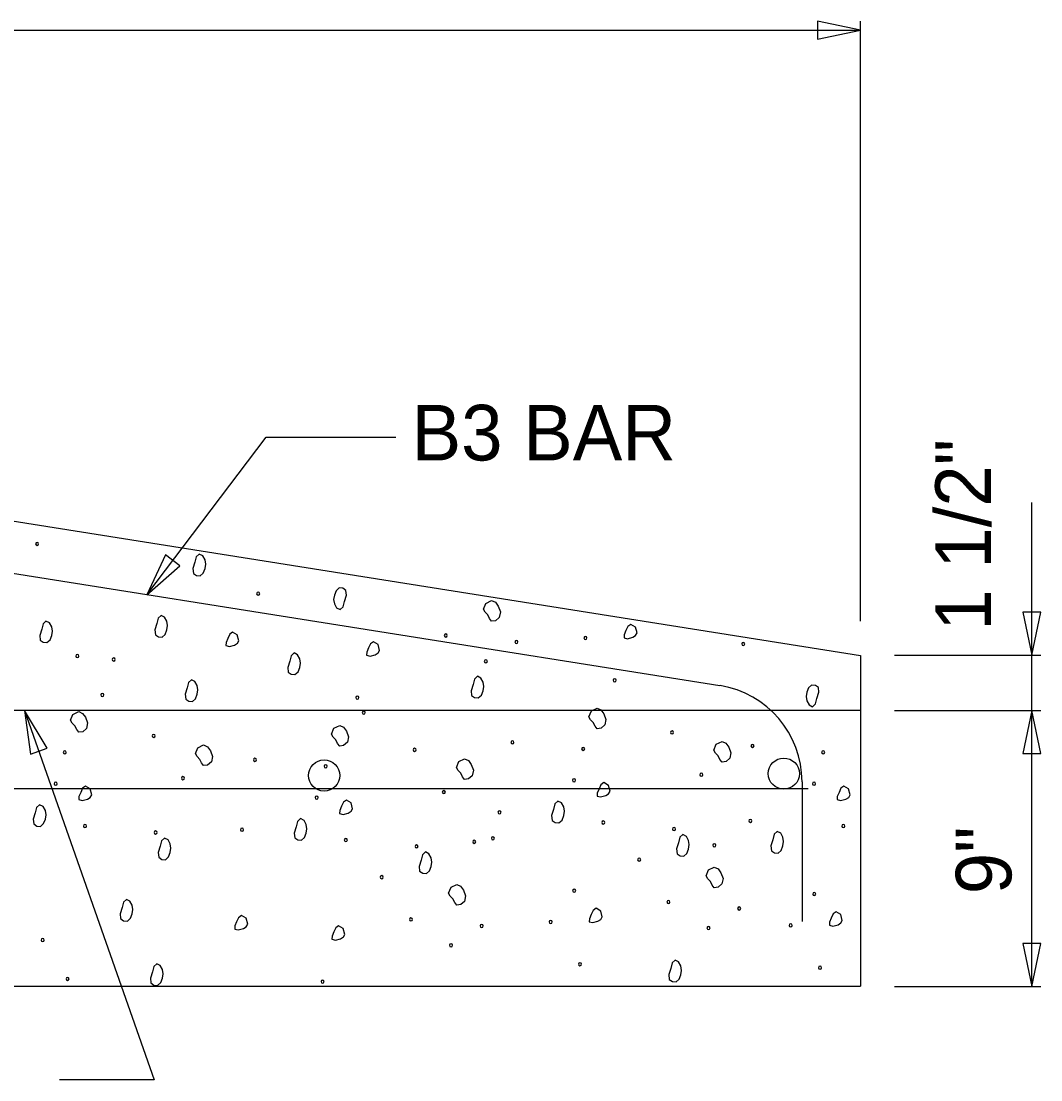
# Model space of a CAD drawing. Extents: x -439.1 to -407.9, y -458.1 to -436.2.
# Drawn here: x -419.155 to -416.404, y -449.316 to -446.46 of the extents above; entities that cross this region are included whole.
import ezdxf

# ---------------------------------------------------------------- set-up
doc = ezdxf.new("R2010")
doc.units = 0
doc.layers.add('Level 4', color=7, linetype='Continuous')
doc.layers.add('Level 45', color=7, linetype='Continuous')

msp = doc.modelspace()

# ---------------------------------------------------------------- linework, layer by layer
at = {"layer": 'Level 4'}
for p, q in [((-422.391, -446.484), (-416.8905, -446.484)), ((-416.8905, -448.0784), (-416.8905, -446.4599)), ((-423.8016, -447.0755), (-416.8905, -448.1707)), ((-421.8946, -447.5188), (-417.2694, -448.2521)), ((-418.8159, -448.0069), (-418.4942, -447.5818)), ((-418.4942, -447.5818), (-418.144, -447.5818)), ((-416.4279, -448.3192), (-416.4279, -447.7581)), ((-416.8905, -448.1707), (-416.8905, -449.0632)), ((-416.7987, -448.1703), (-416.4038, -448.1703)), ((-423.8016, -448.3187), (-416.8905, -448.3187)), ((-419.1455, -448.3192), (-418.7961, -449.3155)), ((-416.7987, -448.3192), (-416.4038, -448.3192)), ((-416.4279, -449.0637), (-416.4279, -448.3192)), ((-417.048, -448.5114), (-417.048, -448.8889)), ((-423.8016, -448.5298), (-417.0312, -448.5298)), ((-423.8016, -449.0632), (-416.8905, -449.0632)), ((-416.7987, -449.0637), (-416.4038, -449.0637)), ((-418.7961, -449.3155), (-419.0512, -449.3155))]:
    msp.add_line(p, q, dxfattribs=at)
for points in [[(-417.0067, -446.5081), (-416.8905, -446.484), (-417.0067, -446.4599)], [(-418.7651, -447.8997), (-418.8159, -448.0069), (-418.7266, -447.9288)], [(-418.6744, -447.8974), (-418.6823, -447.9049), (-418.6861, -447.9195), (-418.6914, -447.9363), (-418.69, -447.9493), (-418.6818, -447.9549), (-418.6718, -447.9558), (-418.6634, -447.9484), (-418.6588, -447.9364), (-418.657, -447.9246), (-418.6588, -447.913), (-418.6648, -447.9022), (-418.6744, -447.8974)], [(-418.2944, -448.0472), (-418.2864, -448.0397), (-418.2827, -448.0251), (-418.2774, -448.0083), (-418.2788, -447.9952), (-418.287, -447.9896), (-418.297, -447.9888), (-418.3054, -447.9961), (-418.3099, -448.0082), (-418.3118, -448.02), (-418.3099, -448.0316), (-418.3039, -448.0424), (-418.2944, -448.0472)], [(-417.9079, -448.046), (-417.9013, -448.0303), (-417.8858, -448.0227), (-417.8755, -448.0275), (-417.8677, -448.0383), (-417.862, -448.0535), (-417.8651, -448.0681), (-417.8751, -448.077), (-417.8858, -448.0785), (-417.8913, -448.0714), (-417.8962, -448.0616), (-417.9032, -448.054), (-417.9079, -448.046)], [(-416.452, -448.0541), (-416.4279, -448.1703), (-416.4038, -448.0541)], [(-419.0879, -448.0779), (-419.0958, -448.0853), (-419.0995, -448.0999), (-419.1048, -448.1167), (-419.1034, -448.1298), (-419.0952, -448.1354), (-419.0853, -448.1363), (-419.0768, -448.1289), (-419.0723, -448.1168), (-419.0705, -448.1051), (-419.0723, -448.0934), (-419.0783, -448.0826), (-419.0879, -448.0779)], [(-418.7772, -448.063), (-418.7852, -448.0704), (-418.7889, -448.085), (-418.7942, -448.1018), (-418.7928, -448.1149), (-418.7846, -448.1205), (-418.7747, -448.1214), (-418.7662, -448.114), (-418.7617, -448.1019), (-418.7598, -448.0902), (-418.7617, -448.0785), (-418.7677, -448.0677), (-418.7772, -448.063)], [(-417.5102, -448.0869), (-417.5179, -448.0928), (-417.5231, -448.1038), (-417.5279, -448.115), (-417.5283, -448.1232), (-417.5188, -448.1256), (-417.505, -448.1219), (-417.4972, -448.1172), (-417.4933, -448.1102), (-417.4975, -448.0943), (-417.5102, -448.0869)], [(-418.5844, -448.1078), (-418.5922, -448.1137), (-418.5974, -448.1247), (-418.6022, -448.136), (-418.6026, -448.1442), (-418.5931, -448.1465), (-418.5792, -448.1429), (-418.5715, -448.1381), (-418.5676, -448.1312), (-418.5718, -448.1153), (-418.5844, -448.1078)], [(-418.2047, -448.1338), (-418.2125, -448.1397), (-418.2177, -448.1507), (-418.2225, -448.1619), (-418.2229, -448.1702), (-418.2134, -448.1725), (-418.1995, -448.1689), (-418.1918, -448.1641), (-418.1878, -448.1572), (-418.1921, -448.1412), (-418.2047, -448.1338)], [(-418.4187, -448.1641), (-418.4266, -448.1716), (-418.4304, -448.1862), (-418.4357, -448.203), (-418.4343, -448.216), (-418.4261, -448.2216), (-418.4161, -448.2225), (-418.4077, -448.2151), (-418.4031, -448.2031), (-418.4013, -448.1913), (-418.4031, -448.1797), (-418.4091, -448.1689), (-418.4187, -448.1641)], [(-417.9241, -448.227), (-417.9321, -448.2344), (-417.9358, -448.2491), (-417.9411, -448.2658), (-417.9397, -448.2789), (-417.9315, -448.2845), (-417.9216, -448.2854), (-417.9131, -448.278), (-417.9086, -448.2659), (-417.9067, -448.2542), (-417.9086, -448.2426), (-417.9146, -448.2317), (-417.9241, -448.227)], [(-418.6955, -448.2364), (-418.7034, -448.2438), (-418.7072, -448.2584), (-418.7125, -448.2752), (-418.711, -448.2883), (-418.7029, -448.2939), (-418.6929, -448.2948), (-418.6844, -448.2874), (-418.6799, -448.2753), (-418.6781, -448.2636), (-418.6799, -448.252), (-418.6859, -448.2411), (-418.6955, -448.2364)], [(-417.0195, -448.309), (-417.0115, -448.3015), (-417.0078, -448.2869), (-417.0025, -448.2701), (-417.0039, -448.2571), (-417.0121, -448.2515), (-417.0221, -448.2506), (-417.0305, -448.2579), (-417.035, -448.27), (-417.0369, -448.2818), (-417.035, -448.2934), (-417.029, -448.3042), (-417.0195, -448.309)], [(-417.623, -448.3361), (-417.6165, -448.3204), (-417.601, -448.3128), (-417.5907, -448.3176), (-417.5828, -448.3283), (-417.5771, -448.3436), (-417.5802, -448.3582), (-417.5902, -448.367), (-417.601, -448.3686), (-417.6064, -448.3615), (-417.6114, -448.3517), (-417.6184, -448.3441), (-417.623, -448.3361)], [(-419.0843, -448.4209), (-419.1455, -448.3192), (-419.1298, -448.4368)], [(-419.0216, -448.3455), (-419.015, -448.3298), (-418.9995, -448.3221), (-418.9892, -448.327), (-418.9813, -448.3377), (-418.9756, -448.353), (-418.9787, -448.3676), (-418.9888, -448.3764), (-418.9995, -448.378), (-419.005, -448.3709), (-419.0099, -448.3611), (-419.0169, -448.3535), (-419.0216, -448.3455)], [(-416.4038, -448.4354), (-416.4279, -448.3192), (-416.452, -448.4354)], [(-418.3176, -448.3831), (-418.311, -448.3673), (-418.2955, -448.3597), (-418.2853, -448.3645), (-418.2774, -448.3753), (-418.2717, -448.3905), (-418.2748, -448.4051), (-418.2848, -448.414), (-418.2955, -448.4155), (-418.301, -448.4084), (-418.3059, -448.3986), (-418.3129, -448.391), (-418.3176, -448.3831)], [(-418.6845, -448.4355), (-418.678, -448.4198), (-418.6625, -448.4121), (-418.6522, -448.417), (-418.6443, -448.4277), (-418.6386, -448.443), (-418.6417, -448.4576), (-418.6517, -448.4664), (-418.6625, -448.468), (-418.6679, -448.4609), (-418.6729, -448.4511), (-418.6799, -448.4435), (-418.6845, -448.4355)], [(-417.286, -448.4261), (-417.2794, -448.4104), (-417.2639, -448.4028), (-417.2536, -448.4076), (-417.2458, -448.4183), (-417.2401, -448.4336), (-417.2432, -448.4482), (-417.2532, -448.457), (-417.2639, -448.4586), (-417.2694, -448.4515), (-417.2743, -448.4417), (-417.2813, -448.4341), (-417.286, -448.4261)], [(-417.9806, -448.4731), (-417.974, -448.4573), (-417.9585, -448.4497), (-417.9482, -448.4545), (-417.9403, -448.4653), (-417.9346, -448.4805), (-417.9377, -448.4951), (-417.9478, -448.504), (-417.9585, -448.5055), (-417.964, -448.4985), (-417.9689, -448.4886), (-417.9759, -448.4811), (-417.9806, -448.4731)], [(-417.5828, -448.5139), (-417.5906, -448.5198), (-417.5958, -448.5308), (-417.6006, -448.542), (-417.601, -448.5502), (-417.5915, -448.5526), (-417.5776, -448.5489), (-417.5699, -448.5442), (-417.5659, -448.5373), (-417.5702, -448.5213), (-417.5828, -448.5139)], [(-418.9814, -448.5233), (-418.9891, -448.5292), (-418.9943, -448.5401), (-418.9991, -448.5514), (-418.9995, -448.5596), (-418.99, -448.562), (-418.9762, -448.5583), (-418.9684, -448.5536), (-418.9645, -448.5466), (-418.9687, -448.5307), (-418.9814, -448.5233)], [(-416.9352, -448.5233), (-416.943, -448.5292), (-416.9481, -448.5401), (-416.9529, -448.5514), (-416.9533, -448.5596), (-416.9439, -448.562), (-416.93, -448.5583), (-416.9222, -448.5536), (-416.9183, -448.5466), (-416.9225, -448.5307), (-416.9352, -448.5233)], [(-418.2774, -448.5608), (-418.2852, -448.5667), (-418.2904, -448.5777), (-418.2951, -448.5889), (-418.2956, -448.5972), (-418.2861, -448.5995), (-418.2722, -448.5959), (-418.2644, -448.5911), (-418.2605, -448.5842), (-418.2648, -448.5682), (-418.2774, -448.5608)], [(-417.7066, -448.564), (-417.7146, -448.5714), (-417.7183, -448.5861), (-417.7236, -448.6028), (-417.7222, -448.6159), (-417.714, -448.6215), (-417.704, -448.6224), (-417.6956, -448.615), (-417.6911, -448.6029), (-417.6892, -448.5912), (-417.6911, -448.5796), (-417.6971, -448.5688), (-417.7066, -448.564)], [(-419.1052, -448.5734), (-419.1131, -448.5808), (-419.1169, -448.5954), (-419.1222, -448.6122), (-419.1208, -448.6253), (-419.1126, -448.6309), (-419.1026, -448.6318), (-419.0942, -448.6244), (-419.0896, -448.6123), (-419.0878, -448.6006), (-419.0896, -448.589), (-419.0956, -448.5781), (-419.1052, -448.5734)], [(-418.4012, -448.6109), (-418.4092, -448.6184), (-418.4129, -448.633), (-418.4182, -448.6498), (-418.4168, -448.6628), (-418.4086, -448.6684), (-418.3986, -448.6693), (-418.3902, -448.6619), (-418.3856, -448.6499), (-418.3838, -448.6381), (-418.3856, -448.6265), (-418.3917, -448.6157), (-418.4012, -448.6109)], [(-417.3696, -448.654), (-417.3775, -448.6614), (-417.3813, -448.6761), (-417.3866, -448.6928), (-417.3852, -448.7059), (-417.377, -448.7115), (-417.367, -448.7124), (-417.3586, -448.705), (-417.354, -448.6929), (-417.3522, -448.6812), (-417.354, -448.6696), (-417.36, -448.6588), (-417.3696, -448.654)], [(-417.1151, -448.6458), (-417.123, -448.6533), (-417.1268, -448.6679), (-417.1321, -448.6847), (-417.1307, -448.6978), (-417.1225, -448.7034), (-417.1125, -448.7043), (-417.1041, -448.6969), (-417.0995, -448.6848), (-417.0977, -448.6731), (-417.0995, -448.6614), (-417.1056, -448.6506), (-417.1151, -448.6458)], [(-418.7681, -448.6634), (-418.7761, -448.6708), (-418.7798, -448.6855), (-418.7851, -448.7022), (-418.7837, -448.7153), (-418.7755, -448.7209), (-418.7655, -448.7218), (-418.7571, -448.7144), (-418.7526, -448.7023), (-418.7507, -448.6906), (-418.7526, -448.679), (-418.7586, -448.6681), (-418.7681, -448.6634)], [(-418.0642, -448.7009), (-418.0721, -448.7084), (-418.0759, -448.723), (-418.0812, -448.7398), (-418.0798, -448.7529), (-418.0716, -448.7584), (-418.0616, -448.7593), (-418.0532, -448.752), (-418.0486, -448.7399), (-418.0468, -448.7281), (-418.0486, -448.7165), (-418.0546, -448.7057), (-418.0642, -448.7009)], [(-417.3071, -448.7651), (-417.3005, -448.7494), (-417.285, -448.7417), (-417.2747, -448.7466), (-417.2668, -448.7573), (-417.2611, -448.7726), (-417.2642, -448.7872), (-417.2743, -448.796), (-417.285, -448.7975), (-417.2904, -448.7905), (-417.2954, -448.7807), (-417.3024, -448.7731), (-417.3071, -448.7651)], [(-418.0016, -448.812), (-417.9951, -448.7963), (-417.9796, -448.7886), (-417.9693, -448.7935), (-417.9614, -448.8042), (-417.9557, -448.8195), (-417.9588, -448.8341), (-417.9688, -448.8429), (-417.9796, -448.8445), (-417.985, -448.8374), (-417.9899, -448.8276), (-417.997, -448.82), (-418.0016, -448.812)], [(-418.871, -448.8289), (-418.8789, -448.8364), (-418.8827, -448.851), (-418.888, -448.8678), (-418.8866, -448.8808), (-418.8784, -448.8864), (-418.8684, -448.8873), (-418.86, -448.8799), (-418.8554, -448.8679), (-418.8536, -448.8561), (-418.8554, -448.8445), (-418.8614, -448.8337), (-418.871, -448.8289)], [(-417.6039, -448.8528), (-417.6117, -448.8587), (-417.6169, -448.8697), (-417.6216, -448.881), (-417.6221, -448.8892), (-417.6126, -448.8915), (-417.5987, -448.8879), (-417.5909, -448.8831), (-417.587, -448.8762), (-417.5913, -448.8603), (-417.6039, -448.8528)], [(-418.5605, -448.8724), (-418.5683, -448.8783), (-418.5735, -448.8893), (-418.5782, -448.9006), (-418.5787, -448.9088), (-418.5692, -448.9111), (-418.5553, -448.9075), (-418.5475, -448.9027), (-418.5436, -448.8958), (-418.5479, -448.8799), (-418.5605, -448.8724)], [(-416.9562, -448.8622), (-416.964, -448.8681), (-416.9692, -448.8791), (-416.974, -448.8903), (-416.9744, -448.8986), (-416.9649, -448.9009), (-416.951, -448.8973), (-416.9433, -448.8925), (-416.9394, -448.8856), (-416.9436, -448.8696), (-416.9562, -448.8622)], [(-418.2985, -448.8998), (-418.3062, -448.9057), (-418.3114, -448.9166), (-418.3162, -448.9279), (-418.3166, -448.9361), (-418.3071, -448.9385), (-418.2933, -448.9348), (-418.2855, -448.9301), (-418.2816, -448.9231), (-418.2858, -448.9072), (-418.2985, -448.8998)], [(-416.452, -448.9475), (-416.4279, -449.0637), (-416.4038, -448.9475)], [(-417.3907, -448.993), (-417.3986, -449.0004), (-417.4024, -449.015), (-417.4076, -449.0318), (-417.4062, -449.0449), (-417.398, -449.0505), (-417.3881, -449.0514), (-417.3796, -449.044), (-417.3751, -449.0319), (-417.3733, -449.0202), (-417.3751, -449.0085), (-417.3811, -448.9977), (-417.3907, -448.993)], [(-418.7892, -449.0023), (-418.7971, -449.0098), (-418.8009, -449.0244), (-418.8062, -449.0412), (-418.8048, -449.0543), (-418.7966, -449.0599), (-418.7866, -449.0608), (-418.7782, -449.0534), (-418.7736, -449.0413), (-418.7718, -449.0295), (-418.7736, -449.0179), (-418.7796, -449.0071), (-418.7892, -449.0023)]]:
    msp.add_lwpolyline(points, close=True, dxfattribs=at)
for centre in [(-418.3375, -448.4946), (-417.0973, -448.4896)]:
    msp.add_circle(centre, 0.042, dxfattribs=at)
for centre, radius, start, end in [((-419.1118, -447.8699), 0.00416, 0, 180), ((-419.1118, -447.8699), 0.00416, 180, 0), ((-418.5155, -448.0042), 0.00416, 0, 180), ((-418.5155, -448.0042), 0.00416, 180, 0), ((-418.0093, -448.1169), 0.00416, 0, 180), ((-418.0093, -448.1169), 0.00416, 180, 0), ((-417.8186, -448.1345), 0.00416, 0, 180), ((-417.8186, -448.1345), 0.00416, 180, 0), ((-417.6324, -448.1237), 0.00416, 0, 180), ((-417.6324, -448.1237), 0.00416, 180, 0), ((-417.2067, -448.1398), 0.00416, 0, 180), ((-417.2067, -448.1398), 0.00416, 180, 0), ((-419.0031, -448.1725), 0.00416, 0, 180), ((-419.0031, -448.1725), 0.00416, 180, 0), ((-418.9051, -448.1818), 0.00416, 0, 180), ((-418.9051, -448.1818), 0.00416, 180, 0), ((-417.9012, -448.1867), 0.00416, 0, 180), ((-417.9012, -448.1867), 0.00416, 180, 0), ((-417.5534, -448.2377), 0.00416, 0, 180), ((-417.5534, -448.2377), 0.00416, 180, 0), ((-417.3105, -448.5114), 0.2625, 0, 80.9914), ((-418.936, -448.2774), 0.00416, 0, 180), ((-418.936, -448.2774), 0.00416, 180, 0), ((-418.248, -448.2846), 0.00416, 0, 180), ((-418.248, -448.2846), 0.00416, 180, 0), ((-418.2305, -448.3249), 0.00416, 0, 180), ((-418.2305, -448.3249), 0.00416, 180, 0), ((-418.7973, -448.3878), 0.00416, 0, 180), ((-418.7973, -448.3878), 0.00416, 180, 0), ((-417.3988, -448.3785), 0.00416, 0, 180), ((-417.3988, -448.3785), 0.00416, 180, 0), ((-419.0372, -448.4323), 0.00416, 0, 180), ((-418.0933, -448.4254), 0.00416, 0, 180), ((-418.0933, -448.4254), 0.00416, 180, 0), ((-417.8294, -448.4054), 0.00416, 0, 180), ((-417.8294, -448.4054), 0.00416, 180, 0), ((-417.6386, -448.4229), 0.00416, 0, 180), ((-417.6386, -448.4229), 0.00416, 180, 0), ((-417.1817, -448.4148), 0.00416, 0, 180), ((-417.1817, -448.4148), 0.00416, 180, 0), ((-416.991, -448.4323), 0.00416, 0, 180), ((-419.0372, -448.4323), 0.00416, 180, 0), ((-418.524, -448.4523), 0.00416, 0, 180), ((-418.524, -448.4523), 0.00416, 180, 0), ((-416.991, -448.4323), 0.00416, 180, 0), ((-418.3332, -448.4699), 0.00416, 0, 180), ((-418.3332, -448.4699), 0.00416, 180, 0), ((-419.0617, -448.5169), 0.00416, 0, 180), ((-418.7183, -448.5019), 0.00416, 0, 180), ((-418.7183, -448.5019), 0.00416, 180, 0), ((-417.6632, -448.5075), 0.00416, 0, 180), ((-417.6632, -448.5075), 0.00416, 180, 0), ((-417.3198, -448.4925), 0.00416, 0, 180), ((-417.3198, -448.4925), 0.00416, 180, 0), ((-417.0156, -448.5169), 0.00416, 0, 180), ((-419.0617, -448.5169), 0.00416, 180, 0), ((-418.0144, -448.5394), 0.00416, 0, 180), ((-418.0144, -448.5394), 0.00416, 180, 0), ((-417.0156, -448.5169), 0.00416, 180, 0), ((-418.3578, -448.5544), 0.00416, 0, 180), ((-418.3578, -448.5544), 0.00416, 180, 0), ((-417.8644, -448.5939), 0.00416, 0, 180), ((-417.8644, -448.5939), 0.00416, 180, 0), ((-418.9828, -448.6309), 0.00416, 0, 180), ((-417.5843, -448.6215), 0.00416, 0, 180), ((-417.5843, -448.6215), 0.00416, 180, 0), ((-417.1875, -448.6171), 0.00416, 0, 180), ((-417.1875, -448.6171), 0.00416, 180, 0), ((-416.9366, -448.6309), 0.00416, 0, 180), ((-418.9828, -448.6309), 0.00416, 180, 0), ((-418.792, -448.6484), 0.00416, 0, 180), ((-418.792, -448.6484), 0.00416, 180, 0), ((-418.559, -448.6408), 0.00416, 0, 180), ((-418.559, -448.6408), 0.00416, 180, 0), ((-417.3935, -448.639), 0.00416, 0, 180), ((-417.3935, -448.639), 0.00416, 180, 0), ((-416.9366, -448.6309), 0.00416, 180, 0), ((-418.2788, -448.6684), 0.00416, 0, 180), ((-418.2788, -448.6684), 0.00416, 180, 0), ((-418.0881, -448.686), 0.00416, 0, 180), ((-418.0881, -448.686), 0.00416, 180, 0), ((-417.9325, -448.6736), 0.00416, 0, 180), ((-417.9325, -448.6736), 0.00416, 180, 0), ((-417.8821, -448.664), 0.00416, 0, 180), ((-417.8821, -448.664), 0.00416, 180, 0), ((-417.2849, -448.6829), 0.00416, 0, 180), ((-417.2849, -448.6829), 0.00416, 180, 0), ((-417.4874, -448.7219), 0.00416, 0, 180), ((-417.4874, -448.7219), 0.00416, 180, 0), ((-418.182, -448.7689), 0.00416, 0, 180), ((-418.182, -448.7689), 0.00416, 180, 0), ((-417.6628, -448.8051), 0.00416, 0, 180), ((-417.6628, -448.8051), 0.00416, 180, 0), ((-417.0152, -448.8145), 0.00416, 0, 180), ((-417.0152, -448.8145), 0.00416, 180, 0), ((-417.4085, -448.836), 0.00416, 0, 180), ((-417.4085, -448.836), 0.00416, 180, 0), ((-417.2177, -448.8535), 0.00416, 0, 180), ((-417.2177, -448.8535), 0.00416, 180, 0), ((-418.1031, -448.8829), 0.00416, 0, 180), ((-418.1031, -448.8829), 0.00416, 180, 0), ((-417.7261, -448.8896), 0.00416, 0, 180), ((-417.9123, -448.9004), 0.00416, 0, 180), ((-417.9123, -448.9004), 0.00416, 180, 0), ((-417.7261, -448.8896), 0.00416, 180, 0), ((-417.3004, -448.9058), 0.00416, 0, 180), ((-417.3004, -448.9058), 0.00416, 180, 0), ((-417.0785, -448.899), 0.00416, 0, 180), ((-417.0785, -448.899), 0.00416, 180, 0), ((-419.0969, -448.9385), 0.00416, 0, 180), ((-419.0969, -448.9385), 0.00416, 180, 0), ((-417.995, -448.9527), 0.00416, 0, 180), ((-417.995, -448.9527), 0.00416, 180, 0), ((-417.6472, -449.0037), 0.00416, 0, 180), ((-417.6472, -449.0037), 0.00416, 180, 0), ((-416.9995, -449.0131), 0.00416, 0, 180), ((-416.9995, -449.0131), 0.00416, 180, 0), ((-419.0297, -449.0433), 0.00416, 0, 180), ((-419.0297, -449.0433), 0.00416, 180, 0), ((-418.3417, -449.0506), 0.00416, 0, 180), ((-418.3417, -449.0506), 0.00416, 180, 0)]:
    msp.add_arc(centre, radius, start, end, dxfattribs=at)

# ---------------------------------------------------------------- texts
msp.add_text('B3 BAR', height=0.15, dxfattribs=at).set_placement((-418.1015, -447.6448))
at = {"layer": 'Level 45'}
for s, p in [('1 1/2"', (-416.5386, -448.1041)), ('9"', (-416.4832, -448.8149))]:
    msp.add_text(s, height=0.15, rotation=90, dxfattribs=at).set_placement(p)

doc.saveas('drawing.dxf')
